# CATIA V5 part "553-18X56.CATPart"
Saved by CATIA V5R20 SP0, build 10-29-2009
Part number: 553-18X56
Definition: NONE
Nomenclature: 553-18X56
Source: Unknown
Description: 553-18X56
Bounding box of the stored display mesh (mm): x 0 to 56, y -15.5 to 15.5, z -15.5 to 15.5
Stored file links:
  C:\Users\Utente\Desktop\IO LAVORO\3D X SITO CF\X SITO\PLASTICA\553\553-18X56.CATPart
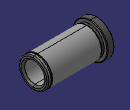
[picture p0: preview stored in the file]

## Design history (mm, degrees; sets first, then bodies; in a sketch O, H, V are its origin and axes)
Body1 "553-18X56" (main body)
  Solid1: solid without history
